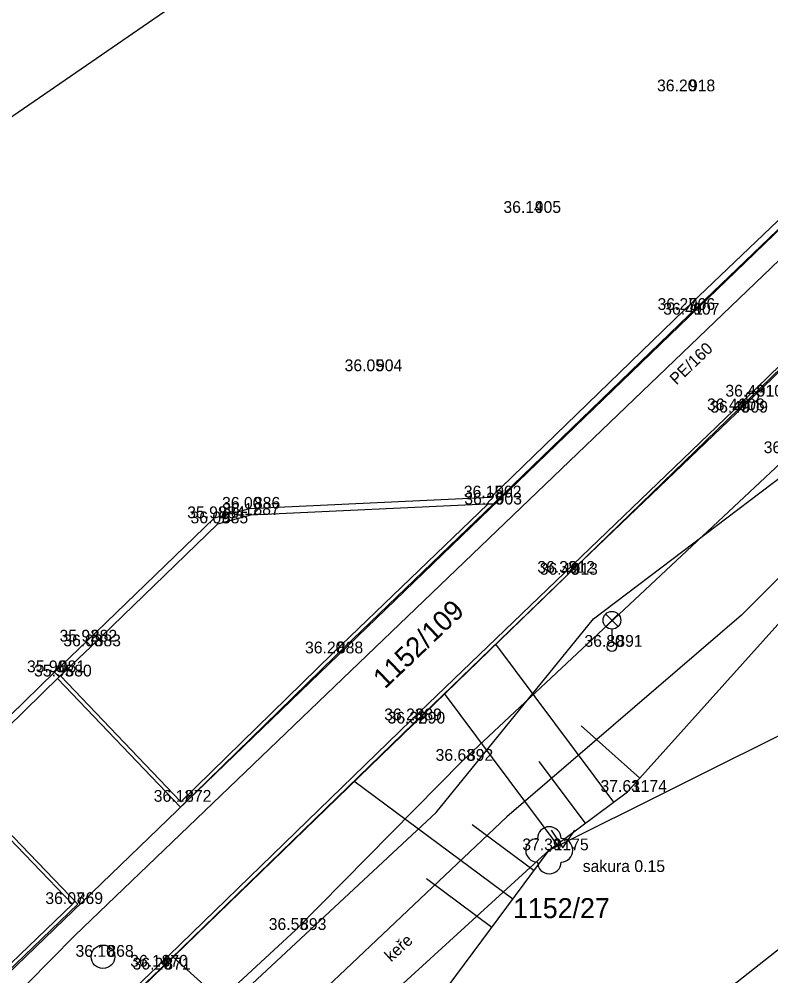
# Model space of a CAD drawing. Extents: x -609709 to -609357, y -1051535 to -1051131.
# Drawn here: x -609619.19 to -609603.24, y -1051267.96 to -1051247.66 of the extents above; entities that cross this region are included whole.
import ezdxf

# ---------------------------------------------------------------- set-up
doc = ezdxf.new("R2010")
doc.units = 0
for name, color, linetype in [('Vrstva 1', 7, 'Continuous'), ('Vrstva 10', 7, 'Continuous'), ('Vrstva 12', 7, 'Continuous'), ('Vrstva 15', 7, 'Continuous'), ('Vrstva 17', 7, 'Continuous'), ('Vrstva 2', 7, 'Continuous'), ('Vrstva 3', 7, 'Continuous'), ('Vrstva 4', 7, 'Continuous'), ('Vrstva 5', 7, 'Continuous'), ('Vrstva 6', 7, 'Continuous'), ('Vrstva 7', 7, 'Continuous'), ('Vrstva 8', 7, 'Continuous')]:
    doc.layers.add(name, color=color, linetype=linetype)

msp = doc.modelspace()

# ---------------------------------------------------------------- linework, layer by layer
at = {"layer": 'Vrstva 1'}
for p, q in [((-609605.07, -1051249.19), (-609605.07, -1051249.19)), ((-609608.34, -1051251.77), (-609608.34, -1051251.77)), ((-609605.07, -1051253.83), (-609605.07, -1051253.83)), ((-609604.98, -1051253.93), (-609604.98, -1051253.93)), ((-609611.71, -1051255.13), (-609611.71, -1051255.13)), ((-609603.63, -1051255.67), (-609603.63, -1051255.67)), ((-609604.02, -1051255.96), (-609604.02, -1051255.96)), ((-609603.95, -1051256.01), (-609603.95, -1051256.01)), ((-609609.18, -1051257.81), (-609609.18, -1051257.81)), ((-609609.17, -1051257.96), (-609609.17, -1051257.96)), ((-609614.31, -1051258.18), (-609614.31, -1051258.18)), ((-609614.3, -1051258.05), (-609614.3, -1051258.05)), ((-609615.05, -1051258.25), (-609615.05, -1051258.25)), ((-609614.98, -1051258.36), (-609614.98, -1051258.36)), ((-609607.62, -1051259.41), (-609607.62, -1051259.41)), ((-609607.56, -1051259.45), (-609607.56, -1051259.45)), ((-609617.76, -1051260.87), (-609617.76, -1051260.87)), ((-609617.68, -1051260.97), (-609617.68, -1051260.97)), ((-609606.61, -1051260.98), (-609606.61, -1051260.98)), ((-609612.54, -1051261.12), (-609612.54, -1051261.12)), ((-609618.44, -1051261.52), (-609618.44, -1051261.52)), ((-609618.3, -1051261.61), (-609618.3, -1051261.61)), ((-609610.87, -1051262.54), (-609610.87, -1051262.54)), ((-609610.8, -1051262.61), (-609610.8, -1051262.61)), ((-609609.78, -1051263.4), (-609609.78, -1051263.4)), ((-609606.28, -1051264.06), (-609606.28, -1051264.06)), ((-609615.76, -1051264.27), (-609615.76, -1051264.27)), ((-609607.94, -1051265.3), (-609607.94, -1051265.3)), ((-609618.06, -1051266.44), (-609618.06, -1051266.44)), ((-609613.32, -1051266.99), (-609613.32, -1051266.99)), ((-609617.41, -1051267.56), (-609617.41, -1051267.56)), ((-609616.26, -1051267.77), (-609616.26, -1051267.77)), ((-609616.2, -1051267.83), (-609616.2, -1051267.83))]:
    msp.add_line(p, q, dxfattribs=at)
at = {"layer": 'Vrstva 10'}
for p, q in [((-609622.18, -1051273.63), (-609589.38, -1051241.83)), ((-609623.53, -1051271.88), (-609592.58, -1051242.01)), ((-609626.15, -1051254.4), (-609615.29, -1051246.93)), ((-609607.9, -1051264.875), (-609607.65, -1051265.25)), ((-609607.65, -1051265.25), (-609607.4, -1051264.875)), ((-609607.9, -1051265.25), (-609607.85, -1051265.25)), ((-609607.45, -1051265.25), (-609607.4, -1051265.25))]:
    msp.add_line(p, q, dxfattribs=at)
at = {"layer": 'Vrstva 12'}
msp.add_lwpolyline([(-609598.88, -1051264.1), (-609604.42, -1051268.47), (-609611.68, -1051274.04), (-609616.21, -1051277.75), (-609621.57, -1051284.12), (-609621.25, -1051285.42), (-609619.8, -1051287.45), (-609615.97, -1051291.57), (-609612.96, -1051295.31), (-609611.54, -1051298.14), (-609609.99, -1051301.94), (-609609.26, -1051303.04), (-609608.61, -1051303.76)], dxfattribs=at)
at = {"layer": 'Vrstva 15'}
for points in [[(-609618.56, -1051272.15), (-609610.34, -1051264.5), (-609607, -1051260.39), (-609602.74, -1051257.16), (-609596.84, -1051252.04), (-609595.4, -1051250.72), (-609595.03, -1051249.91), (-609593.64, -1051247.34), (-609592.3, -1051245.79), (-609590.65, -1051244.31), (-609589.61, -1051243.13), (-609589.45, -1051242.87), (-609588.61, -1051241.92), (-609583.43, -1051237.16), (-609581.27, -1051235.22), (-609579.94, -1051234.39), (-609575.07, -1051232.15), (-609567.92, -1051226.6)], [(-609592.54, -1051249), (-609597.09, -1051253.54), (-609603.86, -1051260.31), (-609608.84, -1051264.59), (-609616.08, -1051271.44), (-609620.11, -1051274.18), (-609621.01, -1051275.83), (-609623.48, -1051278.12), (-609624.89, -1051278.61), (-609626.41, -1051281.76), (-609625.78, -1051282.81), (-609616.94, -1051293.56), (-609613.57, -1051297.39), (-609614.852, -1051298.693)]]:
    msp.add_lwpolyline(points, dxfattribs=at)
at = {"layer": 'Vrstva 17'}
msp.add_lwpolyline([(-609531.786, -1051180.515), (-609532.61, -1051181.07), (-609528.54, -1051185.58), (-609545.95, -1051201.69), (-609546.72, -1051202.27), (-609551.04, -1051206.15), (-609565.42, -1051219.63), (-609579.77, -1051233.3), (-609583.56, -1051235.84), (-609591.75, -1051241.92), (-609609.05, -1051258.52), (-609618.01, -1051267.11), (-609626.05, -1051275.26), (-609630.23, -1051279.58), (-609635.78, -1051285.7), (-609642.85, -1051291.4), (-609672.95, -1051307.23)], dxfattribs=at)
at = {"layer": 'Vrstva 4'}
for p, q in [((-609612.539, -1051261.119), (-609609.242, -1051257.953)), ((-609612.484, -1051261.177), (-609615.762, -1051264.384)), ((-609615.762, -1051264.384), (-609618.373, -1051261.65)), ((-609617.947, -1051266.442), (-609620.529, -1051263.758)), ((-609617.947, -1051266.442), (-609621.175, -1051269.548))]:
    msp.add_line(p, q, dxfattribs=at)
for points in [[(-609602.18, -1051251.07), (-609605.07, -1051253.83), (-609609.18, -1051257.81), (-609614.3, -1051258.05), (-609615.05, -1051258.25), (-609617.76, -1051260.87), (-609618.44, -1051261.52), (-609620.65, -1051263.68), (-609621.37, -1051264.36), (-609621.71, -1051264.87), (-609623.18, -1051267.49), (-609624.27, -1051269.45), (-609624.77, -1051270.32), (-609626.73, -1051273.81), (-609627.2, -1051274.7), (-609627.81, -1051275.78), (-609632.5, -1051279.47)], [(-609602.083, -1051251.171), (-609604.973, -1051253.931), (-609609.121, -1051257.947), (-609614.278, -1051258.189), (-609614.979, -1051258.376), (-609617.663, -1051260.971), (-609618.343, -1051261.621), (-609620.553, -1051263.781), (-609621.262, -1051264.451), (-609621.591, -1051264.943), (-609623.058, -1051267.558), (-609624.148, -1051269.519), (-609624.648, -1051270.389), (-609626.607, -1051273.877), (-609627.077, -1051274.767), (-609627.702, -1051275.873), (-609632.413, -1051279.58)], [(-609601.06, -1051253.08), (-609604.02, -1051255.96), (-609607.62, -1051259.41), (-609610.87, -1051262.54), (-609616.26, -1051267.77), (-609619.52, -1051270.88), (-609621.59, -1051272.88)], [(-609601.004, -1051253.137), (-609603.964, -1051256.018), (-609607.565, -1051259.468), (-609610.814, -1051262.598), (-609616.205, -1051267.828), (-609619.465, -1051270.938), (-609621.528, -1051272.931)], [(-609612.484, -1051261.177), (-609609.121, -1051257.947)], [(-609617.76, -1051260.87), (-609617.663, -1051260.971)], [(-609612.54, -1051261.12), (-609615.76, -1051264.27)], [(-609618.44, -1051261.52), (-609618.343, -1051261.621)], [(-609615.76, -1051264.27), (-609618.315, -1051261.594)], [(-609618.06, -1051266.44), (-609620.587, -1051263.813)], [(-609618.06, -1051266.44), (-609621.23, -1051269.49)]]:
    msp.add_lwpolyline(points, dxfattribs=at)
at = {"layer": 'Vrstva 5'}
for p, q in [((-609606.743, -1051260.55), (-609606.478, -1051260.285)), ((-609606.743, -1051260.285), (-609606.478, -1051260.55)), ((-609606.61, -1051260.605), (-609606.61, -1051260.88))]:
    msp.add_line(p, q, dxfattribs=at)
for centre, radius in [((-609603.63, -1051255.67), 0.125), ((-609606.61, -1051260.417), 0.188), ((-609606.61, -1051260.98), 0.1), ((-609617.41, -1051267.56), 0.25)]:
    msp.add_circle(centre, radius, dxfattribs=at)
at = {"layer": 'Vrstva 6'}
msp.add_lwpolyline([(-609610.31, -1051288.53), (-609610.4, -1051286.73), (-609612.71, -1051282.35), (-609615.84, -1051278.39), (-609617.55, -1051275.92), (-609615.49, -1051274.55), (-609612.49, -1051270.95), (-609610.45, -1051268.68), (-609607.94, -1051265.3), (-609606.28, -1051264.06), (-609602.59, -1051259.95), (-609593.93, -1051248.07), (-609590.64, -1051244.54), (-609589.23, -1051241.892)], dxfattribs=at)
at = {"layer": 'Vrstva 7'}
for points in [[(-609602.81, -1051256.87), (-609609.78, -1051263.4), (-609613.32, -1051266.99), (-609616.49, -1051269.92), (-609618.44, -1051272.03), (-609620.38, -1051273.6), (-609620.1, -1051276.08), (-609618.51, -1051277.17), (-609616.15, -1051276.49)], [(-609612.91, -1051269.83), (-609607.94, -1051265.3), (-609602.48, -1051262.57), (-609602.59, -1051259.95), (-609600.81, -1051258.44), (-609602.81, -1051256.87)]]:
    msp.add_lwpolyline(points, dxfattribs=at)
msp.add_circle((-609607.94, -1051265.3), 0.025, dxfattribs=at)
for centre, start, end in [((-609607.94, -1051265.05), 0, 180), ((-609608.19, -1051265.3), 90, 270), ((-609607.69, -1051265.3), 270, 90), ((-609607.94, -1051265.55), 180, 0)]:
    msp.add_arc(centre, 0.25, start, end, dxfattribs=at)
at = {"layer": 'Vrstva 8'}
for p, q in [((-609606.571, -1051264.277), (-609609.076, -1051260.923)), ((-609607.773, -1051265.175), (-609610.165, -1051261.972)), ((-609606.021, -1051263.772), (-609607.266, -1051262.655)), ((-609607.172, -1051264.726), (-609608.151, -1051263.415)), ((-609608.71, -1051266.336), (-609612.085, -1051263.83)), ((-609608.263, -1051265.734), (-609609.573, -1051264.761)), ((-609609.157, -1051266.939), (-609610.546, -1051265.907)), ((-609612.342, -1051270.786), (-609615.93, -1051267.561))]:
    msp.add_line(p, q, dxfattribs=at)

# ---------------------------------------------------------------- texts
at = {"layer": 'Vrstva 10'}
msp.add_text('1152/109', height=0.425, rotation=43.6643, dxfattribs=at).set_placement((-609611.429, -1051261.891))
msp.add_text('1152/27', height=0.425, dxfattribs=at).set_placement((-609608.71, -1051266.74))
at = {"layer": 'Vrstva 17'}
msp.add_text('PE/160', height=0.25, rotation=43.8171, dxfattribs=at).set_placement((-609605.24, -1051255.435))
at = {"layer": 'Vrstva 2'}
for s, p in [(' 918', (-609605.07, -1051249.19)), (' 905', (-609608.34, -1051251.77)), (' 906', (-609605.07, -1051253.83)), (' 907', (-609604.98, -1051253.93)), (' 904', (-609611.71, -1051255.13)), (' 910', (-609603.63, -1051255.67)), (' 908', (-609604.02, -1051255.96)), (' 909', (-609603.95, -1051256.01)), (' 902', (-609609.18, -1051257.81)), (' 886', (-609614.3, -1051258.05)), (' 903', (-609609.17, -1051257.96)), (' 884', (-609615.05, -1051258.25)), (' 887', (-609614.31, -1051258.18)), (' 885', (-609614.98, -1051258.36)), (' 912', (-609607.62, -1051259.41)), (' 913', (-609607.56, -1051259.45)), (' 882', (-609617.76, -1051260.87)), (' 883', (-609617.68, -1051260.97)), (' 891', (-609606.61, -1051260.98)), (' 888', (-609612.54, -1051261.12)), (' 881', (-609618.44, -1051261.52)), (' 880', (-609618.3, -1051261.61)), (' 889', (-609610.87, -1051262.54)), (' 890', (-609610.8, -1051262.61)), (' 892', (-609609.78, -1051263.4)), (' 1174', (-609606.28, -1051264.06)), (' 872', (-609615.76, -1051264.27)), (' 1175', (-609607.94, -1051265.3)), (' 869', (-609618.06, -1051266.44)), (' 893', (-609613.32, -1051266.99)), (' 868', (-609617.41, -1051267.56)), (' 870', (-609616.26, -1051267.77)), (' 871', (-609616.2, -1051267.83))]:
    msp.add_text(s, height=0.25, dxfattribs=at).set_placement(p)
at = {"layer": 'Vrstva 3'}
for s, p in [('36.20', (-609605.653, -1051249.19)), ('36.14', (-609608.913, -1051251.77)), ('36.27', (-609605.643, -1051253.83)), ('36.41', (-609605.522, -1051253.93)), ('36.05', (-609612.283, -1051255.13)), ('36.48', (-609604.203, -1051255.67)), ('36.44', (-609604.593, -1051255.96)), ('36.49', (-609604.523, -1051256.01)), ('36.86', (-609603.389, -1051256.87)), ('36.15', (-609609.753, -1051257.81)), ('36.00', (-609614.883, -1051258.05)), ('36.29', (-609609.743, -1051257.96)), ('35.98', (-609615.623, -1051258.25)), ('36.12', (-609614.883, -1051258.18)), ('36.09', (-609615.553, -1051258.36)), ('36.32', (-609608.193, -1051259.41)), ('36.40', (-609608.143, -1051259.45)), ('35.92', (-609618.333, -1051260.87)), ('36.03', (-609618.253, -1051260.97)), ('36.80', (-609607.193, -1051260.98)), ('36.20', (-609613.123, -1051261.12)), ('35.90', (-609619.023, -1051261.52)), ('35.95', (-609618.873, -1051261.61)), ('36.23', (-609611.443, -1051262.54)), ('36.32', (-609611.373, -1051262.61)), ('36.63', (-609610.353, -1051263.4)), ('37.63', (-609606.853, -1051264.06)), ('36.12', (-609616.333, -1051264.27)), ('37.39', (-609608.513, -1051265.3)), ('36.07', (-609618.633, -1051266.44)), ('36.55', (-609613.893, -1051266.99)), ('36.10', (-609617.993, -1051267.56)), ('36.14', (-609616.833, -1051267.77)), ('36.20', (-609616.783, -1051267.83))]:
    msp.add_text(s, height=0.25, dxfattribs=at).set_placement(p)
at = {"layer": 'Vrstva 7'}
msp.add_text('sakura 0.15', height=0.25, dxfattribs=at).set_placement((-609607.23, -1051265.76))
msp.add_text('keře', height=0.25, rotation=42.3482, dxfattribs=at).set_placement((-609611.295, -1051267.681))

doc.saveas('drawing.dxf')
